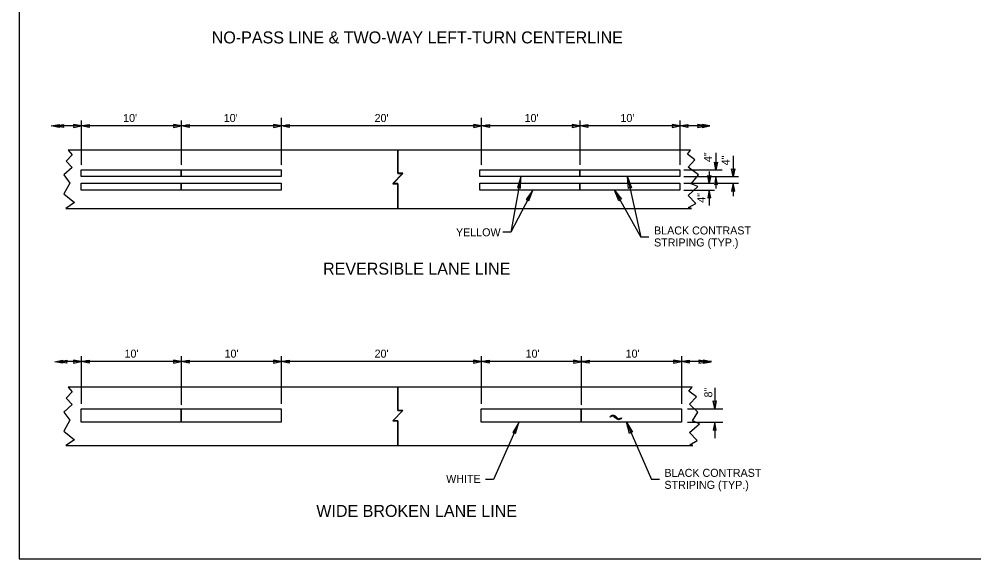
# Model space of a CAD drawing. Extents: x 99754 to 103681, y 99470 to 110996.
# Drawn here: x 99863 to 101772, y 105875 to 106954 of the extents above; entities that cross this region are included whole.
import ezdxf

# ---------------------------------------------------------------- set-up
doc = ezdxf.new("R2010")
doc.units = 0
for name, color, linetype in [('Level 1', 7, 'Continuous'), ('Level 15', 7, 'Continuous'), ('Level 2', 7, 'Continuous'), ('Level 20', 7, 'Continuous'), ('Level 6', 7, 'Continuous'), ('Level 60', 7, 'Continuous'), ('Level 7', 7, 'Continuous')]:
    doc.layers.add(name, color=color, linetype=linetype)

msp = doc.modelspace()

# ---------------------------------------------------------------- linework, layer by layer
at = {"layer": 'Level 1'}
msp.add_lwpolyline([(99863, 105875), (103152, 105875), (103152, 107951), (99863, 107951)], close=True, dxfattribs=at)
at = {"layer": 'Level 15'}
for p, q in [((99987.2, 106751.4), (99987.2, 106662.7)), ((100187.2, 106751.4), (100187.2, 106662.7)), ((100387.2, 106756.7), (100387.2, 106662.7)), ((100787.2, 106756.7), (100787.2, 106662.7)), ((100984.3, 106751.4), (100984.3, 106662.7)), ((101184.3, 106751.4), (101184.3, 106662.7)), ((99987.2, 106740.7), (99944.3, 106740.7)), ((100187.2, 106740.7), (99987.2, 106740.7)), ((100387.2, 106740.7), (100187.2, 106740.7)), ((100784.3, 106740.7), (100387.2, 106740.7)), ((100984.3, 106740.7), (100787.2, 106740.7)), ((101184.3, 106740.7), (100984.3, 106740.7)), ((101244.3, 106740.7), (101184.3, 106740.7)), ((101244.3, 106740.7), (101184.3, 106740.7)), ((101256.4, 106687), (101256.4, 106652.7)), ((101290.8, 106680.7), (101290.8, 106639.4)), ((101191.9, 106652.7), (101269, 106652.7)), ((101243, 106649.8), (101243, 106626.1)), ((101079.6, 106638.7), (101106.5, 106518.6)), ((101191.9, 106639.4), (101240, 106639.4)), ((101245.9, 106639.4), (101301.5, 106639.4)), ((101256.4, 106639.4), (101256.4, 106615.4)), ((100890.1, 106612.3), (100846, 106528.1)), ((101053.5, 106612.7), (101106.5, 106518.6)), ((101191.9, 106626.1), (101252.4, 106626.1)), ((101191.9, 106612.7), (101253.7, 106612.7)), ((101243, 106612.7), (101243, 106581.9)), ((101259.6, 106626.1), (101301.5, 106626.1)), ((101290.8, 106626.1), (101290.8, 106600.1)), ((100846, 106528.1), (100830, 106528.1)), ((101122.5, 106518.6), (101106.5, 106518.6)), ((99987.2, 106269.5), (99948.7, 106269.5)), ((99987.2, 106280.2), (99987.2, 106185.1)), ((100187.2, 106269.5), (99987.2, 106269.5)), ((100187.2, 106280.2), (100187.2, 106183.1)), ((100187.2, 106280.2), (100187.2, 106185.1)), ((100387.2, 106269.5), (100187.2, 106269.5)), ((100387.2, 106280.2), (100387.2, 106185.1)), ((100787.2, 106269.5), (100387.2, 106269.5)), ((100787.2, 106280.2), (100787.2, 106185.1)), ((100987.2, 106269.5), (100787.2, 106269.5)), ((100987.2, 106280.2), (100987.2, 106183.1)), ((100987.2, 106280.2), (100987.2, 106185.1)), ((101187.2, 106269.5), (100987.2, 106269.5)), ((101187.2, 106280.2), (101187.2, 106185.1)), ((101247.2, 106269.5), (101187.2, 106269.5)), ((101253.9, 106217), (101253.9, 106175.1)), ((101199.2, 106175.1), (101269.9, 106175.1)), ((100862.1, 106147.8), (100811.7, 106033.9)), ((101077.4, 106148.3), (101127.2, 106033.9)), ((101199.2, 106148.4), (101269.9, 106148.4)), ((101253.9, 106142.3), (101253.9, 106116.7)), ((100811.7, 106033.9), (100795.7, 106033.9)), ((101143.2, 106033.9), (101127.2, 106033.9))]:
    msp.add_line(p, q, dxfattribs=at)
for points in [[(99927.2, 106740.7), (99942.9, 106743.8), (99942.2, 106740.7), (99942.9, 106737.6)], [(99936, 106740.7), (99951.7, 106743.8), (99951, 106740.7), (99951.7, 106737.6)], [(99987.6, 106740.7), (99971.9, 106743.8), (99972.6, 106740.7), (99971.9, 106737.6)], [(99987.6, 106740.7), (100003.3, 106743.8), (100002.6, 106740.7), (100003.3, 106737.6)], [(99987.6, 106740.7), (99998.1, 106742.8), (99997.6, 106740.7), (99998.1, 106738.7)], [(100187.6, 106740.7), (100171.9, 106743.8), (100172.6, 106740.7), (100171.9, 106737.6)], [(100187.6, 106740.7), (100203.3, 106743.8), (100202.6, 106740.7), (100203.3, 106737.6)], [(100187.6, 106740.7), (100198.1, 106742.8), (100197.6, 106740.7), (100198.1, 106738.7)], [(100387.6, 106740.7), (100371.9, 106743.8), (100372.6, 106740.7), (100371.9, 106737.6)], [(100387.6, 106740.7), (100403.3, 106743.8), (100402.6, 106740.7), (100403.3, 106737.6)], [(100387.6, 106740.7), (100398.1, 106742.8), (100397.6, 106740.7), (100398.1, 106738.7)], [(100787.6, 106740.7), (100771.9, 106743.8), (100772.6, 106740.7), (100771.9, 106737.6)], [(100787.6, 106740.7), (100803.3, 106743.8), (100802.6, 106740.7), (100803.3, 106737.6)], [(100787.6, 106740.7), (100798.1, 106742.8), (100797.6, 106740.7), (100798.1, 106738.7)], [(100984.6, 106740.7), (100968.9, 106743.8), (100969.6, 106740.7), (100968.9, 106737.6)], [(100984.6, 106740.7), (101000.3, 106743.8), (100999.6, 106740.7), (101000.3, 106737.6)], [(100984.6, 106740.7), (100995.1, 106742.8), (100994.6, 106740.7), (100995.1, 106738.7)], [(101184.6, 106740.9), (101168.9, 106744), (101169.7, 106740.9), (101168.9, 106737.8)], [(101184.6, 106740.9), (101200.4, 106744), (101199.6, 106740.9), (101200.4, 106737.8)], [(101184.6, 106740.9), (101195.1, 106742.9), (101194.6, 106740.9), (101195.1, 106738.8)], [(101235.5, 106740.7), (101219.7, 106743.8), (101220.5, 106740.7), (101219.7, 106737.6)], [(101244.3, 106740.7), (101228.5, 106743.8), (101229.3, 106740.7), (101228.5, 106737.6)], [(101256.4, 106652.7), (101253.3, 106668.5), (101256.4, 106667.7), (101259.5, 106668.5)], [(101290.8, 106639.4), (101287.7, 106655.1), (101290.8, 106654.4), (101293.9, 106655.1)], [(100866.5, 106639.3), (100859.4, 106617.4), (100862.5, 106617.9), (100865.3, 106616.4)], [(101079.6, 106638.7), (101087.6, 106617.1), (101084.5, 106617.5), (101081.8, 106615.8)], [(101243, 106626.1), (101240, 106641.8), (101243, 106641.1), (101246.1, 106641.8)], [(101256.4, 106639.4), (101253.3, 106623.7), (101256.4, 106624.4), (101259.5, 106623.7)], [(100890.4, 106612.7), (100877.2, 106593.8), (100880.3, 106593.4), (100882.5, 106591)], [(101053.5, 106612.7), (101067.2, 106594.2), (101064, 106593.7), (101061.9, 106591.3)], [(101243, 106612.7), (101240, 106597), (101243, 106597.7), (101246.1, 106597)], [(101290.8, 106626.1), (101287.7, 106610.3), (101290.8, 106611.1), (101293.9, 106610.3)], [(99934.2, 106269.4), (99949.9, 106272.5), (99949.1, 106269.4), (99949.9, 106266.3)], [(99942.9, 106269.4), (99958.7, 106272.5), (99957.9, 106269.4), (99958.7, 106266.3)], [(99987.2, 106269.5), (99971.5, 106272.6), (99972.2, 106269.5), (99971.5, 106266.4)], [(99987.2, 106269.5), (100002.9, 106272.6), (100002.2, 106269.5), (100002.9, 106266.4)], [(99987.2, 106269.5), (99997.7, 106271.6), (99997.2, 106269.5), (99997.7, 106267.5)], [(100187.2, 106269.5), (100171.5, 106272.6), (100172.2, 106269.5), (100171.5, 106266.4)], [(100187.2, 106269.5), (100202.9, 106272.6), (100202.2, 106269.5), (100202.9, 106266.4)], [(100187.2, 106269.5), (100197.7, 106271.6), (100197.2, 106269.5), (100197.7, 106267.5)], [(100387.2, 106269.5), (100371.5, 106272.6), (100372.2, 106269.5), (100371.5, 106266.4)], [(100387.2, 106269.5), (100402.9, 106272.6), (100402.2, 106269.5), (100402.9, 106266.4)], [(100387.2, 106269.5), (100397.7, 106271.6), (100397.2, 106269.5), (100397.7, 106267.5)], [(100787.2, 106269.5), (100771.5, 106272.6), (100772.2, 106269.5), (100771.5, 106266.4)], [(100787.2, 106269.5), (100802.9, 106272.6), (100802.2, 106269.5), (100802.9, 106266.4)], [(100787.2, 106269.5), (100797.7, 106271.6), (100797.2, 106269.5), (100797.7, 106267.5)], [(100987.1, 106269.4), (100971.4, 106272.5), (100972.2, 106269.4), (100971.4, 106266.3)], [(100987.1, 106269.4), (101002.9, 106272.5), (101002.1, 106269.4), (101002.9, 106266.3)], [(100987.1, 106269.4), (100997.6, 106271.4), (100997.1, 106269.4), (100997.6, 106267.3)], [(101187.2, 106269.5), (101171.5, 106272.6), (101172.2, 106269.5), (101171.5, 106266.4)], [(101187.2, 106269.5), (101202.9, 106272.6), (101202.2, 106269.5), (101202.9, 106266.4)], [(101187.2, 106269.5), (101197.7, 106271.6), (101197.2, 106269.5), (101197.7, 106267.5)], [(101238, 106269.4), (101222.3, 106272.5), (101223, 106269.4), (101222.3, 106266.3)], [(101246.8, 106269.4), (101231.1, 106272.5), (101231.8, 106269.4), (101231.1, 106266.3)], [(101253.9, 106175.1), (101250.8, 106190.8), (101253.9, 106190.1), (101257, 106190.8)], [(100862.1, 106147.8), (100850.3, 106128.1), (100853.5, 106127.8), (100855.8, 106125.7)], [(101077.4, 106148.3), (101089.2, 106128.5), (101086, 106128.3), (101083.7, 106126.1)], [(101253.9, 106148.4), (101250.8, 106132.7), (101253.9, 106133.4), (101257, 106132.7)]]:
    msp.add_lwpolyline(points, close=True, dxfattribs=at)
msp.add_lwpolyline([(100866.5, 106639.3), (100846, 106528.1)], dxfattribs=at)
at = {"layer": 'Level 2'}
for points in [[(100187.2, 106652.7), (100387.2, 106652.7), (100387.2, 106639.4), (100187.2, 106639.4), (100187.2, 106652.7)], [(100984.3, 106652.7), (101184.3, 106652.7), (101184.3, 106639.4), (101105.4, 106639.4), (100984.3, 106639.4), (100984.3, 106652.7)], [(100187.2, 106626.1), (100387.2, 106626.1), (100387.2, 106612.7), (100308.4, 106612.7), (100187.2, 106612.7), (100187.2, 106626.1)], [(100984.3, 106626.1), (101184.3, 106626.1), (101184.3, 106612.7), (101105.4, 106612.7), (100984.3, 106612.7), (100984.3, 106626.1)], [(100387.2, 106175.1), (100387.2, 106148.4), (100187.2, 106148.4), (100187.2, 106175.1), (100387.2, 106175.1)], [(101087.2, 106148.4), (100987.2, 106148.4), (100987.2, 106175.1), (101187.2, 106175.1), (101187.2, 106148.4), (101087.2, 106148.4)]]:
    msp.add_lwpolyline(points, dxfattribs=at)
at = {"layer": 'Level 20'}
for p, q in [((101045, 106158.6), (101045.6, 106160.6)), ((101048.3, 106160.3), (101045, 106158.6)), ((101045.6, 106160.6), (101047.4, 106161.8)), ((101047.4, 106161.8), (101049.1, 106162.4)), ((101049.9, 106160.6), (101048.3, 106160.3)), ((101049.1, 106162.4), (101050.7, 106162.6)), ((101051.3, 106160.4), (101049.9, 106160.6)), ((101050.7, 106162.6), (101052.4, 106162.3)), ((101052.6, 106159.7), (101051.3, 106160.4)), ((101052.4, 106162.3), (101054.6, 106161.1)), ((101054.4, 106158), (101052.6, 106159.7)), ((101057.6, 106155), (101054.4, 106158)), ((101054.6, 106161.1), (101057.5, 106158.3)), ((101057.5, 106158.3), (101059.3, 106156.6)), ((101060, 106153.7), (101057.6, 106155)), ((101059.3, 106156.6), (101061, 106155.6)), ((101061.8, 106153.4), (101060, 106153.7)), ((101061, 106155.6), (101062.3, 106155.4)), ((101063.5, 106153.6), (101061.8, 106153.4)), ((101062.3, 106155.4), (101063.7, 106155.5)), ((101065.1, 106154.2), (101063.5, 106153.6)), ((101063.7, 106155.5), (101065.3, 106156.2)), ((101066.8, 106155.3), (101065.1, 106154.2)), ((101065.3, 106156.2), (101067.4, 106157.4)), ((101067.4, 106157.4), (101066.8, 106155.3))]:
    msp.add_line(p, q, dxfattribs=at)
at = {"layer": 'Level 6'}
for points in [[(99987.2, 106652.7), (100187.2, 106652.7), (100187.2, 106639.4), (99987.2, 106639.4), (99987.2, 106652.7)], [(100784.3, 106652.7), (100984.3, 106652.7), (100984.3, 106639.4), (100905.4, 106639.4), (100784.3, 106639.4), (100784.3, 106652.7)], [(99987.2, 106626.1), (100187.2, 106626.1), (100187.2, 106612.7), (100108.4, 106612.7), (99987.2, 106612.7), (99987.2, 106626.1)], [(100784.3, 106626.1), (100984.3, 106626.1), (100984.3, 106612.7), (100905.4, 106612.7), (100784.3, 106612.7), (100784.3, 106626.1)], [(100187.2, 106175.1), (100187.2, 106148.4), (99987.2, 106148.4), (99987.2, 106175.1), (100187.2, 106175.1)], [(100887.2, 106148.4), (100787.2, 106148.4), (100787.2, 106175.1), (100987.2, 106175.1), (100987.2, 106148.4), (100887.2, 106148.4)]]:
    msp.add_lwpolyline(points, dxfattribs=at)
at = {"layer": 'Level 60'}
msp.add_line((99863, 105875), (99863, 105875), dxfattribs=at)
at = {"layer": 'Level 7'}
for p, q in [((100620.3, 106692.4), (99960.9, 106692.4)), ((101205.8, 106692.4), (100620.3, 106692.4)), ((100620.3, 106625.4), (100610, 106625.4)), ((100620.3, 106576), (100620.3, 106625.4)), ((100620.3, 106625.3), (100620.3, 106576)), ((99956.6, 106576), (100620.3, 106576)), ((100620.3, 106576), (101207.5, 106576)), ((100620.3, 106218.2), (99960.8, 106218.2)), ((101208.7, 106218.2), (100620.3, 106218.2)), ((100620.3, 106151.3), (100610, 106151.3)), ((100620.3, 106101.8), (100620.3, 106151.3)), ((100620.3, 106151.2), (100620.3, 106101.8)), ((99956.6, 106101.8), (100620.3, 106101.8)), ((100620.3, 106101.8), (101210.4, 106101.8))]:
    msp.add_line(p, q, dxfattribs=at)
for points in [[(99960.9, 106692.4), (99969.2, 106683.1), (99956.8, 106670.5), (99969.2, 106658), (99952.2, 106642.8), (99964.2, 106626.6), (99952.5, 106604.9), (99973.6, 106587.6), (99956.6, 106576)], [(100610, 106625.4), (100630.6, 106646.1), (100620.3, 106646.1), (100620.3, 106692.4)], [(100620.3, 106692.4), (100620.3, 106646), (100630.6, 106646)], [(101207.5, 106576), (101201.2, 106577.6), (101216, 106585.9), (101200.9, 106601.9), (101220.2, 106619.4), (101206.8, 106625.3), (101221.8, 106642.7), (101200.6, 106658.6), (101214.4, 106673), (101199.4, 106684.3), (101205.8, 106692.4)], [(100630.6, 106646), (100610, 106625.3), (100620.3, 106625.3)], [(99960.8, 106218.2), (99969.2, 106209), (99956.8, 106196.3), (99969.2, 106183.9), (99952.2, 106168.6), (99964.2, 106152.5), (99952.5, 106130.7), (99973.6, 106113.4), (99956.6, 106101.8)], [(100610, 106151.3), (100630.6, 106171.9), (100620.3, 106171.9), (100620.3, 106218.2)], [(100620.3, 106218.2), (100620.3, 106171.8), (100630.6, 106171.8)], [(101210.4, 106101.8), (101204.1, 106103.4), (101219, 106111.8), (101203.8, 106127.7), (101223.2, 106145.2), (101209.8, 106151.1), (101220.1, 106168.6), (101203.5, 106184.5), (101217.4, 106198.9), (101202.4, 106210.2), (101208.7, 106218.2)], [(100630.6, 106171.8), (100610, 106151.2), (100620.3, 106151.2)]]:
    msp.add_lwpolyline(points, dxfattribs=at)

# ---------------------------------------------------------------- texts
at = {"layer": 'Level 20'}
for s, height, p in [('NO-PASS LINE & TWO-WAY LEFT-TURN CENTERLINE', 24, (100248.2, 106905.8)), ("10'", 16, (100071, 106748.7)), ("10'", 16, (100272.2, 106748.7)), ("20'", 16, (100573.8, 106748.7)), ("10'", 16, (100873.8, 106748.7)), ("10'", 16, (101065.4, 106748.7)), ('YELLOW', 16, (100736.6, 106520.1)), ('BLACK CONTRAST ', 16, (101132.6, 106523.8)), ('STRIPING (TYP.)', 16, (101132.6, 106499.8)), ('REVERSIBLE LANE LINE', 24, (100470.8, 106443.4)), ("10'", 16, (100073.8, 106277.5)), ("10'", 16, (100273.8, 106277.5)), ("20'", 16, (100573.8, 106277.5)), ("10'", 16, (100875.8, 106277.5)), ("10'", 16, (101075.8, 106277.5)), ('BLACK CONTRAST ', 16, (101153.4, 106039.1)), ('WHITE', 16, (100717, 106027.1)), ('STRIPING (TYP.)', 16, (101153.4, 106015.1)), ('WIDE BROKEN LANE LINE', 24, (100457.3, 105959))]:
    msp.add_text(s, height=height, dxfattribs=at).set_placement(p)
for s, p in [('4"', (101248.4, 106668.5)), ('4"', (101283.5, 106662.1)), ('4"', (101235, 106587.2)), ('8"', (101249.1, 106197.8))]:
    msp.add_text(s, height=16, rotation=90, dxfattribs=at).set_placement(p)

doc.saveas('drawing.dxf')
